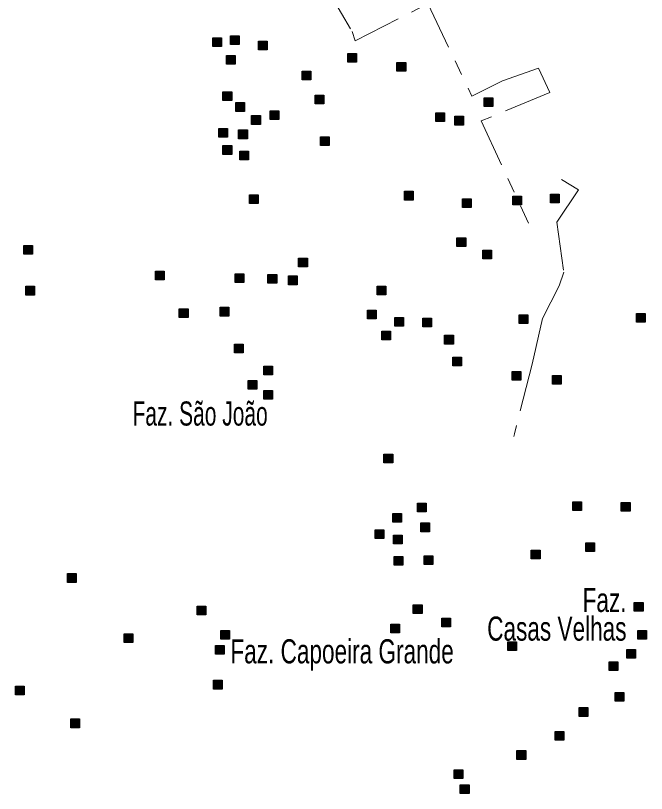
# Model space of a CAD drawing. Extents: x 445.4 to 500, y 8728.7 to 8784.
# Drawn here: x 467.9 to 472.09, y 8752.63 to 8757.8 of the extents above; entities that cross this region are included whole.
import ezdxf
from ezdxf.enums import TextEntityAlignment as Align

# ---------------------------------------------------------------- set-up
doc = ezdxf.new("R2010")
doc.units = 0
doc.header["$LTSCALE"] = 0.064
doc.linetypes.add('DOT_DASHED', pattern=[7.7, 5, -1.2, 0.3, -1.2])
doc.layers.add('2', color=7, linetype='Continuous', lineweight=25)
doc.layers.add('22', color=7, linetype='DOT_DASHED', lineweight=13)
doc.layers.add('61', color=7, linetype='Continuous')

msp = doc.modelspace()

# ---------------------------------------------------------------- hatches: boundary and pattern name
at = {"layer": '2'}
for points in [[(469.2092, 8757.6483), (469.2672, 8757.6483), (469.2672, 8757.5903), (469.2092, 8757.5903)], [(469.3269, 8757.6619), (469.3849, 8757.6619), (469.3849, 8757.6039), (469.3269, 8757.6039)], [(469.5124, 8757.6257), (469.5704, 8757.6257), (469.5704, 8757.5677), (469.5124, 8757.5677)], [(469.2997, 8757.5306), (469.3577, 8757.5306), (469.3577, 8757.4726), (469.2997, 8757.4726)], [(470.1052, 8757.5442), (470.1632, 8757.5442), (470.1632, 8757.4862), (470.1052, 8757.4862)], [(470.4312, 8757.4853), (470.4892, 8757.4853), (470.4892, 8757.4273), (470.4312, 8757.4273)], [(469.802, 8757.4265), (469.86, 8757.4265), (469.86, 8757.3685), (469.802, 8757.3685)], [(469.2771, 8757.2907), (469.3351, 8757.2907), (469.3351, 8757.2327), (469.2771, 8757.2327)], [(469.888, 8757.268), (469.946, 8757.268), (469.946, 8757.21), (469.888, 8757.21)], [(469.3631, 8757.2182), (469.4211, 8757.2182), (469.4211, 8757.1602), (469.3631, 8757.1602)], [(471.0102, 8757.2499), (471.0682, 8757.2499), (471.0682, 8757.1919), (471.0102, 8757.1919)], [(469.5893, 8757.1639), (469.6473, 8757.1639), (469.6473, 8757.1059), (469.5893, 8757.1059)], [(469.4672, 8757.1322), (469.5252, 8757.1322), (469.5252, 8757.0742), (469.4672, 8757.0742)], [(470.6884, 8757.1503), (470.7464, 8757.1503), (470.7464, 8757.0923), (470.6884, 8757.0923)], [(470.8156, 8757.1277), (470.8736, 8757.1277), (470.8736, 8757.0697), (470.8156, 8757.0697)], [(469.25, 8757.0462), (469.308, 8757.0462), (469.308, 8756.9882), (469.25, 8756.9882)], [(469.3812, 8757.0371), (469.4392, 8757.0371), (469.4392, 8756.9791), (469.3812, 8756.9791)], [(469.9242, 8756.9919), (469.9822, 8756.9919), (469.9822, 8756.9339), (469.9242, 8756.9339)], [(469.2771, 8756.933), (469.3351, 8756.933), (469.3351, 8756.875), (469.2771, 8756.875)], [(469.3893, 8756.8968), (469.4473, 8756.8968), (469.4473, 8756.8388), (469.3893, 8756.8388)], [(469.4536, 8756.607), (469.5116, 8756.607), (469.5116, 8756.549), (469.4536, 8756.549)], [(470.4808, 8756.6297), (470.5388, 8756.6297), (470.5388, 8756.5717), (470.4808, 8756.5717)], [(471.2002, 8756.598), (471.2582, 8756.598), (471.2582, 8756.54), (471.2002, 8756.54)], [(471.4491, 8756.6116), (471.5071, 8756.6116), (471.5071, 8756.5536), (471.4491, 8756.5536)], [(470.8654, 8756.5799), (470.9234, 8756.5799), (470.9234, 8756.5219), (470.8654, 8756.5219)], [(470.8292, 8756.3218), (470.8872, 8756.3218), (470.8872, 8756.2638), (470.8292, 8756.2638)], [(467.9558, 8756.271), (468.0138, 8756.271), (468.0138, 8756.213), (467.9558, 8756.213)], [(471.0011, 8756.2403), (471.0591, 8756.2403), (471.0591, 8756.1823), (471.0011, 8756.1823)], [(469.7794, 8756.186), (469.8374, 8756.186), (469.8374, 8756.128), (469.7794, 8756.128)], [(468.8291, 8756.0999), (468.8871, 8756.0999), (468.8871, 8756.0419), (468.8291, 8756.0419)], [(469.3586, 8756.0818), (469.4166, 8756.0818), (469.4166, 8756.0238), (469.3586, 8756.0238)], [(469.5758, 8756.0773), (469.6338, 8756.0773), (469.6338, 8756.0193), (469.5758, 8756.0193)], [(469.7115, 8756.0683), (469.7695, 8756.0683), (469.7695, 8756.0103), (469.7115, 8756.0103)], [(467.9694, 8755.9994), (468.0274, 8755.9994), (468.0274, 8755.9414), (467.9694, 8755.9414)], [(470.2998, 8756.0003), (470.3578, 8756.0003), (470.3578, 8755.9423), (470.2998, 8755.9423)], [(468.9875, 8755.8509), (469.0455, 8755.8509), (469.0455, 8755.7929), (468.9875, 8755.7929)], [(469.259, 8755.86), (469.317, 8755.86), (469.317, 8755.802), (469.259, 8755.802)], [(470.2364, 8755.8419), (470.2944, 8755.8419), (470.2944, 8755.7839), (470.2364, 8755.7839)], [(472.0193, 8755.8192), (472.0773, 8755.8192), (472.0773, 8755.7612), (472.0193, 8755.7612)], [(470.4174, 8755.7921), (470.4754, 8755.7921), (470.4754, 8755.7341), (470.4174, 8755.7341)], [(470.6029, 8755.7876), (470.6609, 8755.7876), (470.6609, 8755.7296), (470.6029, 8755.7296)], [(471.241, 8755.8102), (471.299, 8755.8102), (471.299, 8755.7522), (471.241, 8755.7522)], [(470.3314, 8755.7015), (470.3894, 8755.7015), (470.3894, 8755.6435), (470.3314, 8755.6435)], [(470.7477, 8755.6744), (470.8057, 8755.6744), (470.8057, 8755.6164), (470.7477, 8755.6164)], [(469.354, 8755.6155), (469.412, 8755.6155), (469.412, 8755.5575), (469.354, 8755.5575)], [(470.802, 8755.5295), (470.86, 8755.5295), (470.86, 8755.4715), (470.802, 8755.4715)], [(469.5486, 8755.4706), (469.6066, 8755.4706), (469.6066, 8755.4126), (469.5486, 8755.4126)], [(471.1957, 8755.4344), (471.2537, 8755.4344), (471.2537, 8755.3764), (471.1957, 8755.3764)], [(471.4627, 8755.4073), (471.5207, 8755.4073), (471.5207, 8755.3493), (471.4627, 8755.3493)], [(469.4445, 8755.3756), (469.5025, 8755.3756), (469.5025, 8755.3176), (469.4445, 8755.3176)], [(469.5486, 8755.3076), (469.6066, 8755.3076), (469.6066, 8755.2496), (469.5486, 8755.2496)], [(470.345, 8754.8866), (470.403, 8754.8866), (470.403, 8754.8286), (470.345, 8754.8286)], [(470.5667, 8754.5606), (470.6247, 8754.5606), (470.6247, 8754.5026), (470.5667, 8754.5026)], [(471.5984, 8754.5697), (471.6564, 8754.5697), (471.6564, 8754.5117), (471.5984, 8754.5117)], [(471.9197, 8754.5651), (471.9777, 8754.5651), (471.9777, 8754.5071), (471.9197, 8754.5071)], [(470.4038, 8754.4927), (470.4618, 8754.4927), (470.4618, 8754.4347), (470.4038, 8754.4347)], [(470.5894, 8754.4293), (470.6474, 8754.4293), (470.6474, 8754.3713), (470.5894, 8754.3713)], [(470.2862, 8754.384), (470.3442, 8754.384), (470.3442, 8754.326), (470.2862, 8754.326)], [(470.4084, 8754.3478), (470.4664, 8754.3478), (470.4664, 8754.2898), (470.4084, 8754.2898)], [(471.6844, 8754.298), (471.7424, 8754.298), (471.7424, 8754.24), (471.6844, 8754.24)], [(471.3224, 8754.2482), (471.3804, 8754.2482), (471.3804, 8754.1902), (471.3224, 8754.1902)], [(470.4129, 8754.2075), (470.4709, 8754.2075), (470.4709, 8754.1495), (470.4129, 8754.1495)], [(470.612, 8754.212), (470.67, 8754.212), (470.67, 8754.154), (470.612, 8754.154)], [(468.2454, 8754.0933), (468.3034, 8754.0933), (468.3034, 8754.0353), (468.2454, 8754.0353)], [(469.1052, 8753.877), (469.1632, 8753.877), (469.1632, 8753.819), (469.1052, 8753.819)], [(470.5396, 8753.886), (470.5976, 8753.886), (470.5976, 8753.828), (470.5396, 8753.828)], [(472.0057, 8753.9014), (472.0637, 8753.9014), (472.0637, 8753.8434), (472.0057, 8753.8434)], [(470.3903, 8753.7575), (470.4483, 8753.7575), (470.4483, 8753.6995), (470.3903, 8753.6995)], [(470.7296, 8753.7982), (470.7876, 8753.7982), (470.7876, 8753.7402), (470.7296, 8753.7402)], [(469.2635, 8753.7167), (469.3215, 8753.7167), (469.3215, 8753.6587), (469.2635, 8753.6587)], [(472.0283, 8753.7167), (472.0863, 8753.7167), (472.0863, 8753.6587), (472.0283, 8753.6587)], [(468.621, 8753.6941), (468.679, 8753.6941), (468.679, 8753.6361), (468.621, 8753.6361)], [(469.2273, 8753.6171), (469.2853, 8753.6171), (469.2853, 8753.5591), (469.2273, 8753.5591)], [(471.1658, 8753.6409), (471.2238, 8753.6409), (471.2238, 8753.5829), (471.1658, 8753.5829)], [(471.9559, 8753.59), (472.0139, 8753.59), (472.0139, 8753.532), (471.9559, 8753.532)], [(471.8383, 8753.5075), (471.8963, 8753.5075), (471.8963, 8753.4495), (471.8383, 8753.4495)], [(467.9015, 8753.3463), (467.9595, 8753.3463), (467.9595, 8753.2883), (467.9015, 8753.2883)], [(469.2138, 8753.3853), (469.2718, 8753.3853), (469.2718, 8753.3273), (469.2138, 8753.3273)], [(471.879, 8753.3038), (471.937, 8753.3038), (471.937, 8753.2458), (471.879, 8753.2458)], [(471.6392, 8753.2042), (471.6972, 8753.2042), (471.6972, 8753.1462), (471.6392, 8753.1462)], [(468.268, 8753.129), (468.326, 8753.129), (468.326, 8753.071), (468.268, 8753.071)], [(471.4808, 8753.0457), (471.5388, 8753.0457), (471.5388, 8752.9877), (471.4808, 8752.9877)], [(471.2274, 8752.9189), (471.2854, 8752.9189), (471.2854, 8752.8609), (471.2274, 8752.8609)], [(470.8111, 8752.7922), (470.8691, 8752.7922), (470.8691, 8752.7342), (470.8111, 8752.7342)], [(470.8518, 8752.6926), (470.9098, 8752.6926), (470.9098, 8752.6346), (470.8518, 8752.6346)]]:
    msp.add_hatch(color=256, dxfattribs=at).paths.add_polyline_path(points)

# ---------------------------------------------------------------- linework, layer by layer
for points in [[(469.2092, 8757.6483), (469.2672, 8757.6483), (469.2672, 8757.5903), (469.2092, 8757.5903)], [(469.3269, 8757.6619), (469.3849, 8757.6619), (469.3849, 8757.6039), (469.3269, 8757.6039)], [(469.5124, 8757.6257), (469.5704, 8757.6257), (469.5704, 8757.5677), (469.5124, 8757.5677)], [(469.2997, 8757.5306), (469.3577, 8757.5306), (469.3577, 8757.4726), (469.2997, 8757.4726)], [(470.1052, 8757.5442), (470.1632, 8757.5442), (470.1632, 8757.4862), (470.1052, 8757.4862)], [(470.4312, 8757.4853), (470.4892, 8757.4853), (470.4892, 8757.4273), (470.4312, 8757.4273)], [(469.802, 8757.4265), (469.86, 8757.4265), (469.86, 8757.3685), (469.802, 8757.3685)], [(469.2771, 8757.2907), (469.3351, 8757.2907), (469.3351, 8757.2327), (469.2771, 8757.2327)], [(469.888, 8757.268), (469.946, 8757.268), (469.946, 8757.21), (469.888, 8757.21)], [(469.3631, 8757.2182), (469.4211, 8757.2182), (469.4211, 8757.1602), (469.3631, 8757.1602)], [(471.0102, 8757.2499), (471.0682, 8757.2499), (471.0682, 8757.1919), (471.0102, 8757.1919)], [(469.5893, 8757.1639), (469.6473, 8757.1639), (469.6473, 8757.1059), (469.5893, 8757.1059)], [(469.4672, 8757.1322), (469.5252, 8757.1322), (469.5252, 8757.0742), (469.4672, 8757.0742)], [(470.6884, 8757.1503), (470.7464, 8757.1503), (470.7464, 8757.0923), (470.6884, 8757.0923)], [(470.8156, 8757.1277), (470.8736, 8757.1277), (470.8736, 8757.0697), (470.8156, 8757.0697)], [(469.25, 8757.0462), (469.308, 8757.0462), (469.308, 8756.9882), (469.25, 8756.9882)], [(469.3812, 8757.0371), (469.4392, 8757.0371), (469.4392, 8756.9791), (469.3812, 8756.9791)], [(469.9242, 8756.9919), (469.9822, 8756.9919), (469.9822, 8756.9339), (469.9242, 8756.9339)], [(469.2771, 8756.933), (469.3351, 8756.933), (469.3351, 8756.875), (469.2771, 8756.875)], [(469.3893, 8756.8968), (469.4473, 8756.8968), (469.4473, 8756.8388), (469.3893, 8756.8388)], [(469.4536, 8756.607), (469.5116, 8756.607), (469.5116, 8756.549), (469.4536, 8756.549)], [(470.4808, 8756.6297), (470.5388, 8756.6297), (470.5388, 8756.5717), (470.4808, 8756.5717)], [(471.2002, 8756.598), (471.2582, 8756.598), (471.2582, 8756.54), (471.2002, 8756.54)], [(471.4491, 8756.6116), (471.5071, 8756.6116), (471.5071, 8756.5536), (471.4491, 8756.5536)], [(470.8654, 8756.5799), (470.9234, 8756.5799), (470.9234, 8756.5219), (470.8654, 8756.5219)], [(470.8292, 8756.3218), (470.8872, 8756.3218), (470.8872, 8756.2638), (470.8292, 8756.2638)], [(467.9558, 8756.271), (468.0138, 8756.271), (468.0138, 8756.213), (467.9558, 8756.213)], [(471.0011, 8756.2403), (471.0591, 8756.2403), (471.0591, 8756.1823), (471.0011, 8756.1823)], [(469.7794, 8756.186), (469.8374, 8756.186), (469.8374, 8756.128), (469.7794, 8756.128)], [(468.8291, 8756.0999), (468.8871, 8756.0999), (468.8871, 8756.0419), (468.8291, 8756.0419)], [(469.3586, 8756.0818), (469.4166, 8756.0818), (469.4166, 8756.0238), (469.3586, 8756.0238)], [(469.5758, 8756.0773), (469.6338, 8756.0773), (469.6338, 8756.0193), (469.5758, 8756.0193)], [(469.7115, 8756.0683), (469.7695, 8756.0683), (469.7695, 8756.0103), (469.7115, 8756.0103)], [(467.9694, 8755.9994), (468.0274, 8755.9994), (468.0274, 8755.9414), (467.9694, 8755.9414)], [(470.2998, 8756.0003), (470.3578, 8756.0003), (470.3578, 8755.9423), (470.2998, 8755.9423)], [(468.9875, 8755.8509), (469.0455, 8755.8509), (469.0455, 8755.7929), (468.9875, 8755.7929)], [(469.259, 8755.86), (469.317, 8755.86), (469.317, 8755.802), (469.259, 8755.802)], [(470.2364, 8755.8419), (470.2944, 8755.8419), (470.2944, 8755.7839), (470.2364, 8755.7839)], [(472.0193, 8755.8192), (472.0773, 8755.8192), (472.0773, 8755.7612), (472.0193, 8755.7612)], [(470.4174, 8755.7921), (470.4754, 8755.7921), (470.4754, 8755.7341), (470.4174, 8755.7341)], [(470.6029, 8755.7876), (470.6609, 8755.7876), (470.6609, 8755.7296), (470.6029, 8755.7296)], [(471.241, 8755.8102), (471.299, 8755.8102), (471.299, 8755.7522), (471.241, 8755.7522)], [(470.3314, 8755.7015), (470.3894, 8755.7015), (470.3894, 8755.6435), (470.3314, 8755.6435)], [(470.7477, 8755.6744), (470.8057, 8755.6744), (470.8057, 8755.6164), (470.7477, 8755.6164)], [(469.354, 8755.6155), (469.412, 8755.6155), (469.412, 8755.5575), (469.354, 8755.5575)], [(470.802, 8755.5295), (470.86, 8755.5295), (470.86, 8755.4715), (470.802, 8755.4715)], [(469.5486, 8755.4706), (469.6066, 8755.4706), (469.6066, 8755.4126), (469.5486, 8755.4126)], [(471.1957, 8755.4344), (471.2537, 8755.4344), (471.2537, 8755.3764), (471.1957, 8755.3764)], [(471.4627, 8755.4073), (471.5207, 8755.4073), (471.5207, 8755.3493), (471.4627, 8755.3493)], [(469.4445, 8755.3756), (469.5025, 8755.3756), (469.5025, 8755.3176), (469.4445, 8755.3176)], [(469.5486, 8755.3076), (469.6066, 8755.3076), (469.6066, 8755.2496), (469.5486, 8755.2496)], [(470.345, 8754.8866), (470.403, 8754.8866), (470.403, 8754.8286), (470.345, 8754.8286)], [(470.5667, 8754.5606), (470.6247, 8754.5606), (470.6247, 8754.5026), (470.5667, 8754.5026)], [(471.5984, 8754.5697), (471.6564, 8754.5697), (471.6564, 8754.5117), (471.5984, 8754.5117)], [(471.9197, 8754.5651), (471.9777, 8754.5651), (471.9777, 8754.5071), (471.9197, 8754.5071)], [(470.4038, 8754.4927), (470.4618, 8754.4927), (470.4618, 8754.4347), (470.4038, 8754.4347)], [(470.5894, 8754.4293), (470.6474, 8754.4293), (470.6474, 8754.3713), (470.5894, 8754.3713)], [(470.2862, 8754.384), (470.3442, 8754.384), (470.3442, 8754.326), (470.2862, 8754.326)], [(470.4084, 8754.3478), (470.4664, 8754.3478), (470.4664, 8754.2898), (470.4084, 8754.2898)], [(471.6844, 8754.298), (471.7424, 8754.298), (471.7424, 8754.24), (471.6844, 8754.24)], [(471.3224, 8754.2482), (471.3804, 8754.2482), (471.3804, 8754.1902), (471.3224, 8754.1902)], [(470.4129, 8754.2075), (470.4709, 8754.2075), (470.4709, 8754.1495), (470.4129, 8754.1495)], [(470.612, 8754.212), (470.67, 8754.212), (470.67, 8754.154), (470.612, 8754.154)], [(468.2454, 8754.0933), (468.3034, 8754.0933), (468.3034, 8754.0353), (468.2454, 8754.0353)], [(469.1052, 8753.877), (469.1632, 8753.877), (469.1632, 8753.819), (469.1052, 8753.819)], [(470.5396, 8753.886), (470.5976, 8753.886), (470.5976, 8753.828), (470.5396, 8753.828)], [(472.0057, 8753.9014), (472.0637, 8753.9014), (472.0637, 8753.8434), (472.0057, 8753.8434)], [(470.3903, 8753.7575), (470.4483, 8753.7575), (470.4483, 8753.6995), (470.3903, 8753.6995)], [(470.7296, 8753.7982), (470.7876, 8753.7982), (470.7876, 8753.7402), (470.7296, 8753.7402)], [(469.2635, 8753.7167), (469.3215, 8753.7167), (469.3215, 8753.6587), (469.2635, 8753.6587)], [(472.0283, 8753.7167), (472.0863, 8753.7167), (472.0863, 8753.6587), (472.0283, 8753.6587)], [(468.621, 8753.6941), (468.679, 8753.6941), (468.679, 8753.6361), (468.621, 8753.6361)], [(469.2273, 8753.6171), (469.2853, 8753.6171), (469.2853, 8753.5591), (469.2273, 8753.5591)], [(471.1658, 8753.6409), (471.2238, 8753.6409), (471.2238, 8753.5829), (471.1658, 8753.5829)], [(471.9559, 8753.59), (472.0139, 8753.59), (472.0139, 8753.532), (471.9559, 8753.532)], [(471.8383, 8753.5075), (471.8963, 8753.5075), (471.8963, 8753.4495), (471.8383, 8753.4495)], [(467.9015, 8753.3463), (467.9595, 8753.3463), (467.9595, 8753.2883), (467.9015, 8753.2883)], [(469.2138, 8753.3853), (469.2718, 8753.3853), (469.2718, 8753.3273), (469.2138, 8753.3273)], [(471.879, 8753.3038), (471.937, 8753.3038), (471.937, 8753.2458), (471.879, 8753.2458)], [(471.6392, 8753.2042), (471.6972, 8753.2042), (471.6972, 8753.1462), (471.6392, 8753.1462)], [(468.268, 8753.129), (468.326, 8753.129), (468.326, 8753.071), (468.268, 8753.071)], [(471.4808, 8753.0457), (471.5388, 8753.0457), (471.5388, 8752.9877), (471.4808, 8752.9877)], [(471.2274, 8752.9189), (471.2854, 8752.9189), (471.2854, 8752.8609), (471.2274, 8752.8609)], [(470.8111, 8752.7922), (470.8691, 8752.7922), (470.8691, 8752.7342), (470.8111, 8752.7342)], [(470.8518, 8752.6926), (470.9098, 8752.6926), (470.9098, 8752.6346), (470.8518, 8752.6346)]]:
    msp.add_lwpolyline(points, close=True, dxfattribs=at)
at = {"layer": '22'}
for points in [[(469.9633, 8757.9837), (470.1344, 8757.6896), (470.1539, 8757.6279), (470.6364, 8757.8751), (470.9285, 8757.2614), (471.1325, 8757.3622), (471.37, 8757.4476), (471.446, 8757.2863), (470.99, 8757.0966), (471.3046, 8756.4178)], [(471.5226, 8756.7087), (471.6366, 8756.6393), (471.4911, 8756.4242), (471.5391, 8756.093), (471.5068, 8756.0023), (471.3976, 8755.7864), (471.3275, 8755.483), (471.2106, 8755.0205), (471.2072, 8755.0032)]]:
    msp.add_lwpolyline(points, dxfattribs=at)

# ---------------------------------------------------------------- texts
at = {"layer": '61'}
for s, width, p in [('Faz. São João', 0.65, (468.6773, 8755.0754)), ('Faz. Capoeira Grande', 0.7, (469.3265, 8753.4975))]:
    msp.add_text(s, height=0.16, dxfattribs=dict(at, width=width)).set_placement(p)
at = {"layer": '61', "width": 0.7}
for s, p in [('              Faz.', (471.9541, 8753.8384)), ('Casas Velhas', (471.9541, 8753.6484))]:
    msp.add_text(s, height=0.16, dxfattribs=at).set_placement(p, align=Align.RIGHT)

doc.saveas('drawing.dxf')
